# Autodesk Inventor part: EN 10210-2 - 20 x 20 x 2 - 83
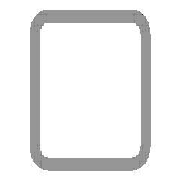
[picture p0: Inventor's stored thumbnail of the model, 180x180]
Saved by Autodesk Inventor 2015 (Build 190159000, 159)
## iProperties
Created: 2015-05
Part Number: EN 10210-2 - 20 x 20 x 2 - 83
Material: Steel, Mild
Description: Tube
Document SubType Name: Modeling
Standard: DIN
Designer: TREINA6
Standard Revision: 1997
Standards Organization: DIN
Language: en-US
Size Designation: 20 x 20 x 2
Categories: <MemberInstance><Categories><Category DisplayName="Structural Shapes" InternalName="089c4875-fa83-4c05-b084-43b9cc11f5ed" Mnemonic="GRDR"><CategoryParameter Dis
Stock Number: 20 x 20 x 2
Density: 7.85 g/cm^3
Appearance: Semi-Polished
IsCustomPart: 1
_CCFamilyMember: 1
_CCFamilyDisplayName: DIN EN 10210-2 (Square) - Tube
_FrameMemberDoc: Frame Member File
_Version: 15.0.0
_GetPNFromCC: 1
Author: TREINA6
G_L: 83,000 mm
G_W: 20,000 mm
G_H: 20,000 mm
+9DF60717-1334-4C68-9413-9DEFD5C3ABD7+CUTDETAIL1: Cut
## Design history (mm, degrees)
node "Start plane"
node "End plane"
sketch "Sketch"
  geometry: L1 (-10, -7)-(-10, 7); L2 (-7, 10)-(7, 10); L3 (10, 7)-(10, -7); L4 (7, -10)-(-7, -10); L5 (-7, 8)-(7, 8); L6 (8, 7)-(8, -7); L7 (7, -8)-(-7, -8); L8 (-8, -7)-(-8, 7); L9 (0, 14.87)-(0, -14.87) reference; L10 (-14.87, 0)-(14.87, 0) reference; A1 r 3 centre (-7, -7) between (-10, -7) and (-7, -10); A2 r 3 centre (-7, 7) between (-7, 10) and (-10, 7); A3 r 3 centre (7, 7) between (10, 7) and (7, 10); A4 r 3 centre (7, -7) between (7, -10) and (10, -7); A5 r 1 centre (-7, 7) between (-7, 8) and (-8, 7); A6 r 1 centre (7, 7) between (8, 7) and (7, 8); A7 r 1 centre (7, -7) between (7, -8) and (8, -7); A8 r 1 centre (-7, -7) between (-8, -7) and (-7, -8)
  constraints: 16 end point, 16 point on circle, 8 centre point, 8 tangent, 4 parallel, 3 equal radius, 2 perpendicular, 7 other
  dimensions: "d7" = 3 radius of A1 (= G_IR); "d10" = 20 distance between parallel lines of L2 L4 (= G_H); "d11" = 20 distance between parallel lines of L1 L3 (= G_W); "d12" = 2 distance between parallel lines of L3 L6 (= G_T); "d15" = 10 distance between parallel lines of L2 L10 (= 0.5 x d10); "d16" = 10 distance between parallel lines of L9 L3 (= 0.5 x d11)
extrude "Body" new body sketch "Sketch" stored distance "d3" = 83 (= G_L); taper "d4" = 0 deg
node "Driven Length"
  sketch "Sketch3"
    geometry: L1 (0, 0)-(10, 0) reference
    constraints: 2 end point, 1 horizontal
  workplane "Work Plane3"
  sketch "Sketch4"
    geometry: L1 (-2, 0)-(12, 0) reference; L2 (-2, 83)-(12, 83) reference
    dimensions: "d18" = 83 distance between parallel lines of L1 L2 (derived)
workplane "Work Plane4"
split "Split1"
body "Solid1"
other parameters: "G_W" = 20 [user parameter; used in 1 equation term], "G_H" = 20 [user parameter; used in 1 equation term], "G_T" = 2 [user parameter; used in 1 equation term], "G_IR" = 3 [user parameter; used in 1 equation term], "G_L" = 83 (= d18) [user parameter; used in 1 equation term], "G_OFFSET_START" = 0 [user parameter; used in 1 equation term], "d13" = 0 (computed from G_OFFSET_START), "d14" = 83 (= G_OFFSET_END + B_L), "B_L" = 103 [user parameter; used in 1 equation term], "d17" = 90 deg
